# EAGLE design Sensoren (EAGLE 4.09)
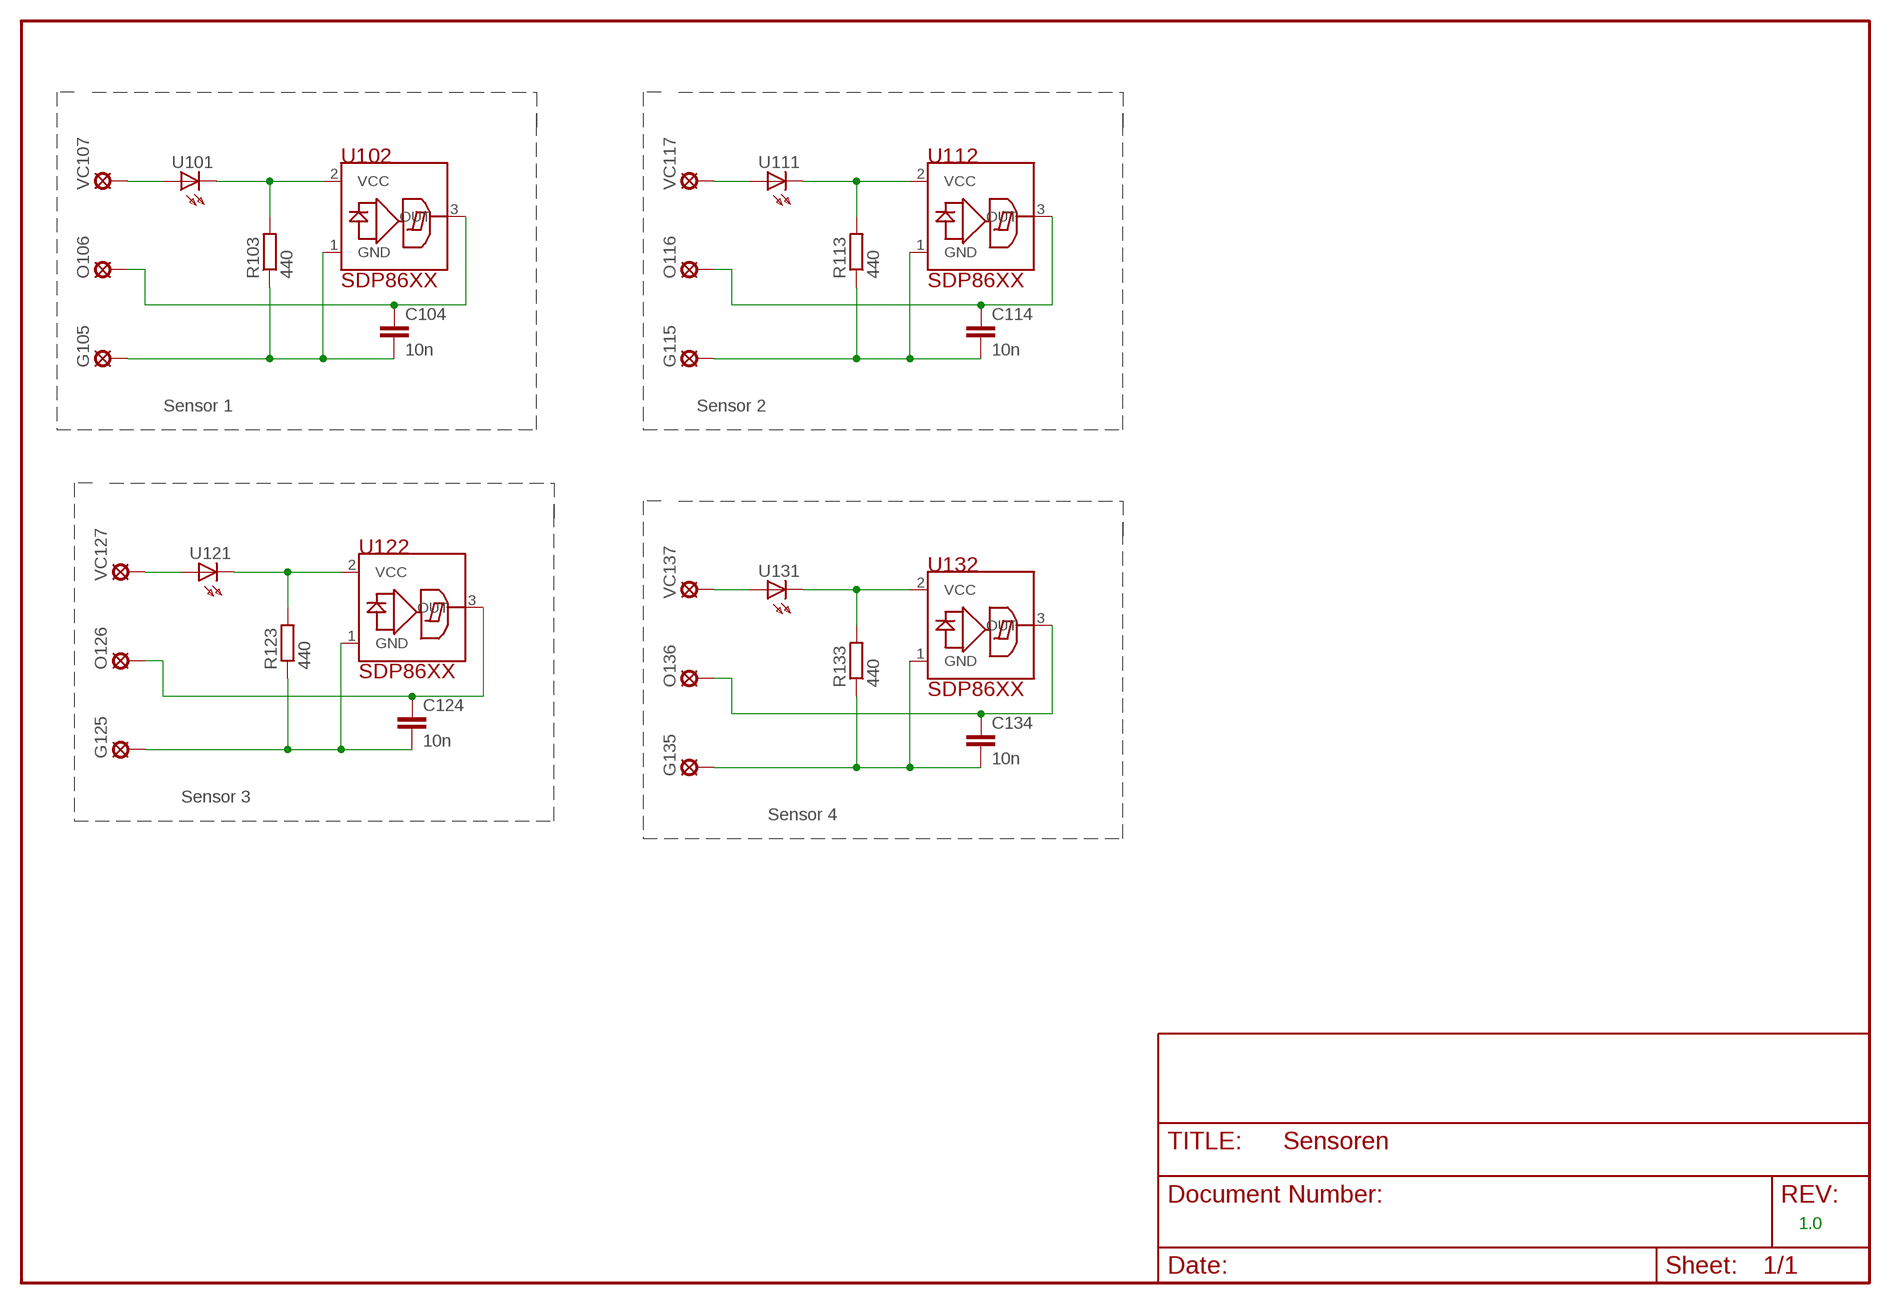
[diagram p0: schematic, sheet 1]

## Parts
C104  10n  C-EUC0805  [C0805]
C114  10n  C-EUC0805  [C0805]
C124  10n  C-EUC0805  [C0805]
C134  10n  C-EUC0805  [C0805]
G105  LSP10  [LSP10]
G115  LSP10  [LSP10]
G125  LSP10  [LSP10]
G135  LSP10  [LSP10]
O106  LSP10  [LSP10]
O116  LSP10  [LSP10]
O126  LSP10  [LSP10]
O136  LSP10  [LSP10]
R103  440  R-EU_R0805  [R0805]
R113  440  R-EU_R0805  [R0805]
R123  440  R-EU_R0805  [R0805]
R133  440  R-EU_R0805  [R0805]
U101  LEDIRL80A  [IRL80A]
U102  SDP86XX  [OPTST]
U111  LEDIRL80A  [IRL80A]
U112  SDP86XX  [OPTST]
U121  LEDIRL80A  [IRL80A]
U122  SDP86XX  [OPTST]
U131  LEDIRL80A  [IRL80A]
U132  SDP86XX  [OPTST]
VC107  LSP10  [LSP10]
VC117  LSP10  [LSP10]
VC127  LSP10  [LSP10]
VC137  LSP10  [LSP10]

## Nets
N$1: C104.2 G105.MP R103.1 U102.1(GND)
N$2: C104.1 O106.MP U102.3(OUT)
N$3: C114.1 O116.MP U112.3(OUT)
N$4: C124.1 O126.MP U122.3(OUT)
N$6: U121.A VC127.MP
N$7: U131.A VC137.MP
N$8: U111.A VC117.MP
N$9: U101.A VC107.MP
N$117: R113.2 U111.K(C) U112.2(VCC)
N$121: C124.2 G125.MP R123.1 U122.1(GND)
N$131: C134.2 G135.MP R133.1 U132.1(GND)
N$135: C134.1 O136.MP U132.3(OUT)
N$137: R123.2 U121.K(C) U122.2(VCC)
N$138: R133.2 U131.K(C) U132.2(VCC)
N$202: C114.2 G115.MP R113.1 U112.1(GND)
VCC: R103.2 U101.K(C) U102.2(VCC)

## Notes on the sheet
- Sensor 1 | Sensor 2
- Sensor 3
- Sensor 4
- 1.0

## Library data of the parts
C104 C114 C124 C134 = rcl:C-EU: CAPACITOR, European symbol
G105 G115 G125 G135 O106 O116 O126 O136 VC107 VC117 VC127 VC137 = solpad:LSP10: SOLDER PAD
R103 R113 R123 R133 = rcl:R-EU_: RESISTOR, European symbol
U101 U111 U121 U131 = led:LED: LED
U102 U112 U122 U132 = enertex:SDP86XX: Optoschmitt Trigger Dector

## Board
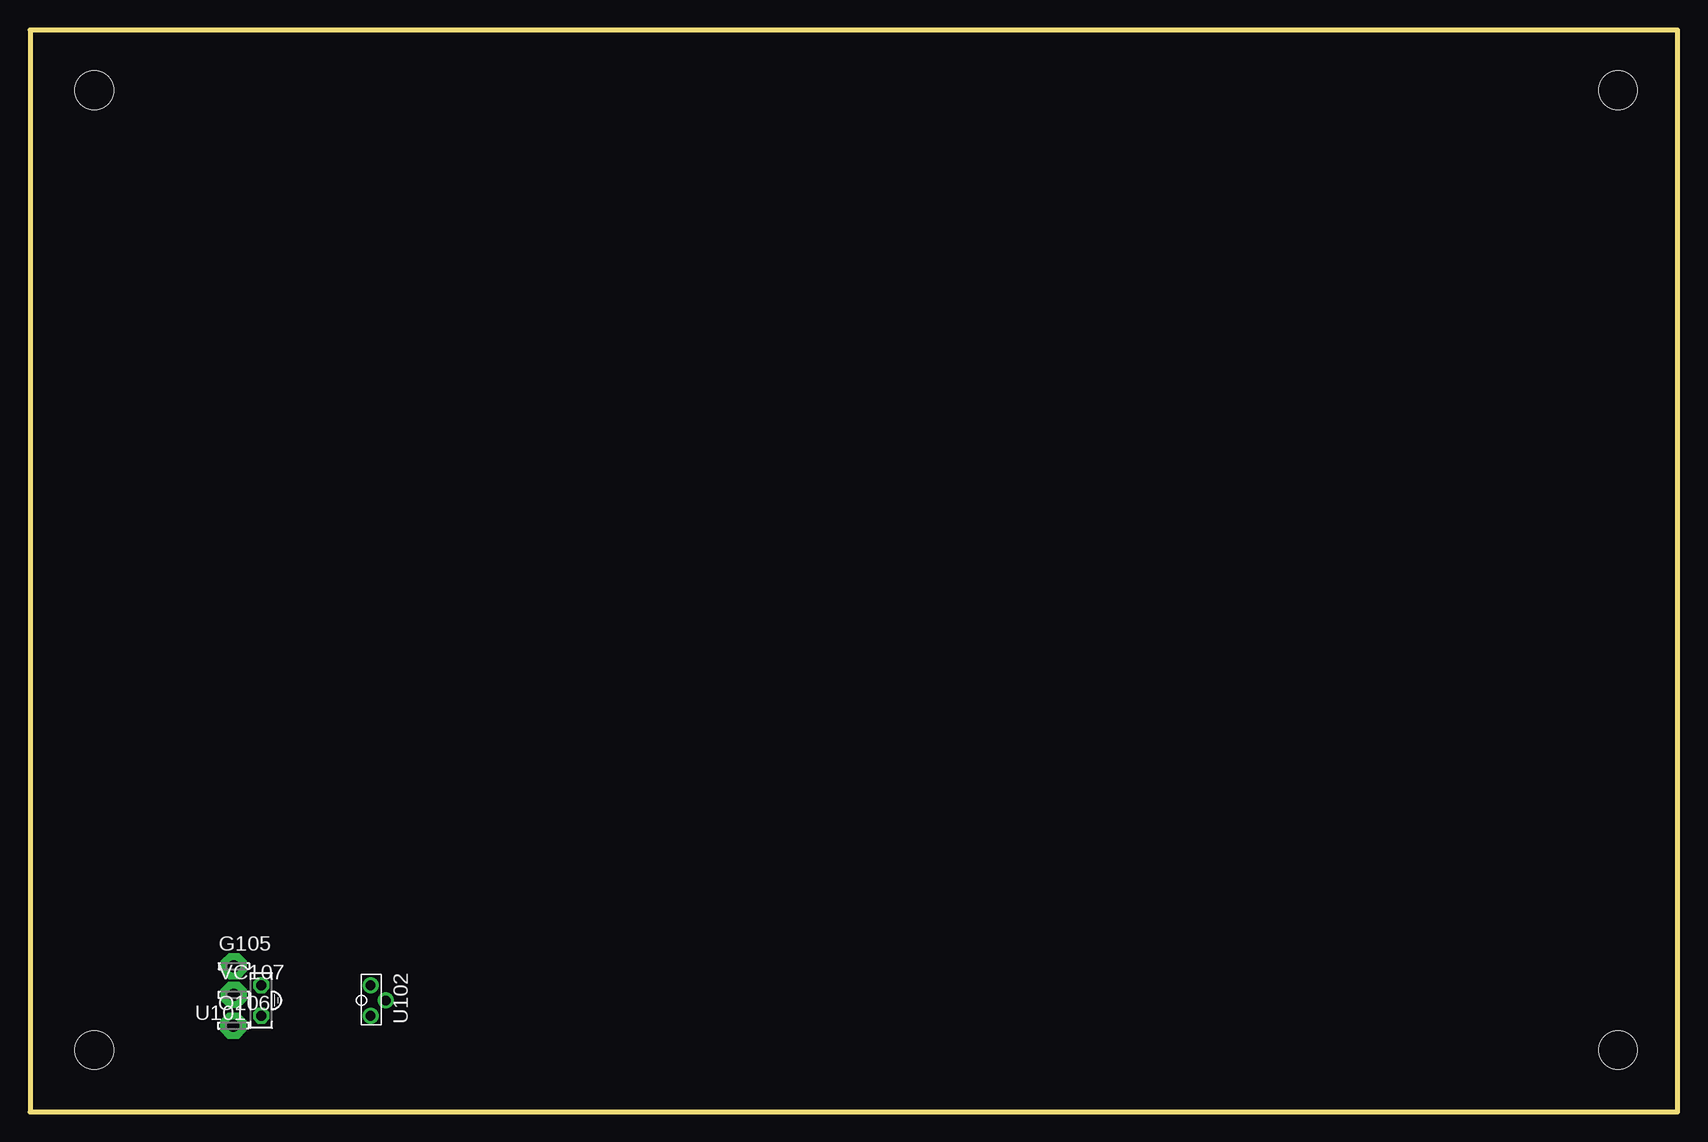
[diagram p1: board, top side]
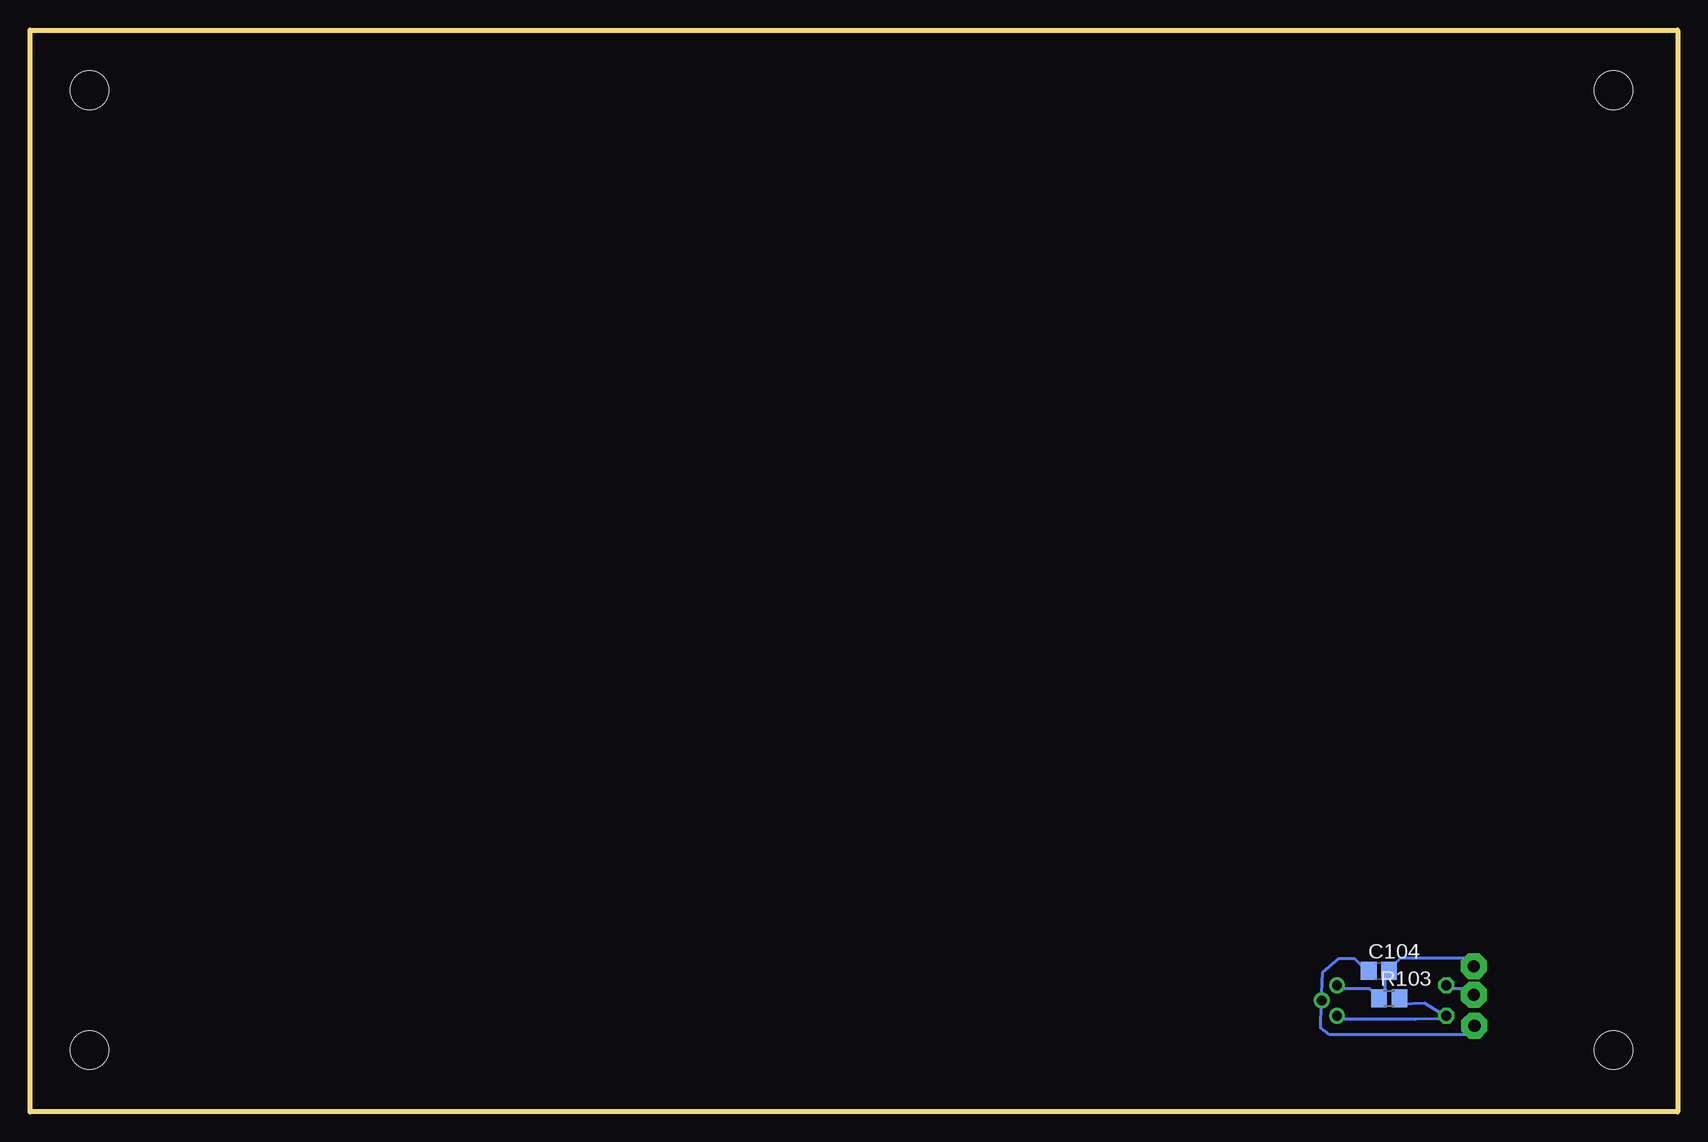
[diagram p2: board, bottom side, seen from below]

Size 137.3 x 90.19 mm. Coordinates in mm from the lower left corner, seen from the top.
Outline: 0,0 137.3,0 137.3,90.19 0,90.19 0,0
Copper layers used: Bottom
Holes 3.2 mm at 5.35,85.17 5.35,5.16 132.35,5.16 132.35,85.17

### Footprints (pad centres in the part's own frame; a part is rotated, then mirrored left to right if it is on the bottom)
C0805 = smd 1.3 x 1.5: 1 -0.85,0; 2 0.85,0
LSP10 = drill 1.016 pad 2.159 octagon: MP 0,0
R0805 = smd 1.3 x 1.5: 1 -0.85,0; 2 0.85,0
IRL80A = drill 0.813 octagon: A 0,-1.27; K 0,1.27
OPTST = drill 0.813 round: 1 -1.27,0; 2 1.27,0; 3 0,1.27

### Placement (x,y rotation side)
C104  24.89,11.74 0 bottom
C114  not placed on the board
C124  not placed on the board
C134  not placed on the board
G105  16.99,12.14 0 top
G115  not placed on the board
G125  not placed on the board
G135  not placed on the board
O106  16.93,7.18 0 top
O116  not placed on the board
O126  not placed on the board
O136  not placed on the board
R103  24.04,9.47 0 bottom
R113  not placed on the board
R123  not placed on the board
R133  not placed on the board
U101  19.27,9.28 180 top
U102  28.38,9.28 270 top
U111  not placed on the board
U112  not placed on the board
U121  not placed on the board
U122  not placed on the board
U131  not placed on the board
U132  not placed on the board
VC107  16.98,9.75 0 top
VC117  not placed on the board
VC127  not placed on the board
VC137  not placed on the board

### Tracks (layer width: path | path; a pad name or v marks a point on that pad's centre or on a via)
N$1
  Bottom 0.254: 24.4,8.97 25.67,10.24 28.21,10.24 U102.1 | 24.4,11.51 24.4,8.97 | 24.4,8.97 R103.1 | 24.4,11.51 23.13,12.78 16.78,12.78 G105.MP | 24.4,11.51 C104.2
N$2
  Bottom 0.254: 29.68,9.07 29.58,11.61 28.21,12.78 26.94,12.78 25.67,11.51 C104.1 | 29.68,9.07 29.75,7 28.98,6.43 16.78,6.43 O106.MP | 29.68,9.07 U102.3
N$3  (2 unrouted)
N$4  (2 unrouted)
N$6  (1 unrouted)
N$7  (1 unrouted)
N$8  (1 unrouted)
N$9
  Bottom 0.254: U101.A 19.32,10.24 16.78,10.24 VC107.MP
N$117  (2 unrouted)
N$121  (3 unrouted)
N$131  (3 unrouted)
N$135  (2 unrouted)
N$137  (2 unrouted)
N$138  (2 unrouted)
N$202  (3 unrouted)
VCC
  Bottom 0.254: 18.99,7.77 21.06,9.04 23.13,8.97 R103.2 | 18.99,7.77 19.32,7.7 U101.K | 18.99,7.77 21.86,7.7 28.21,7.7 U102.2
